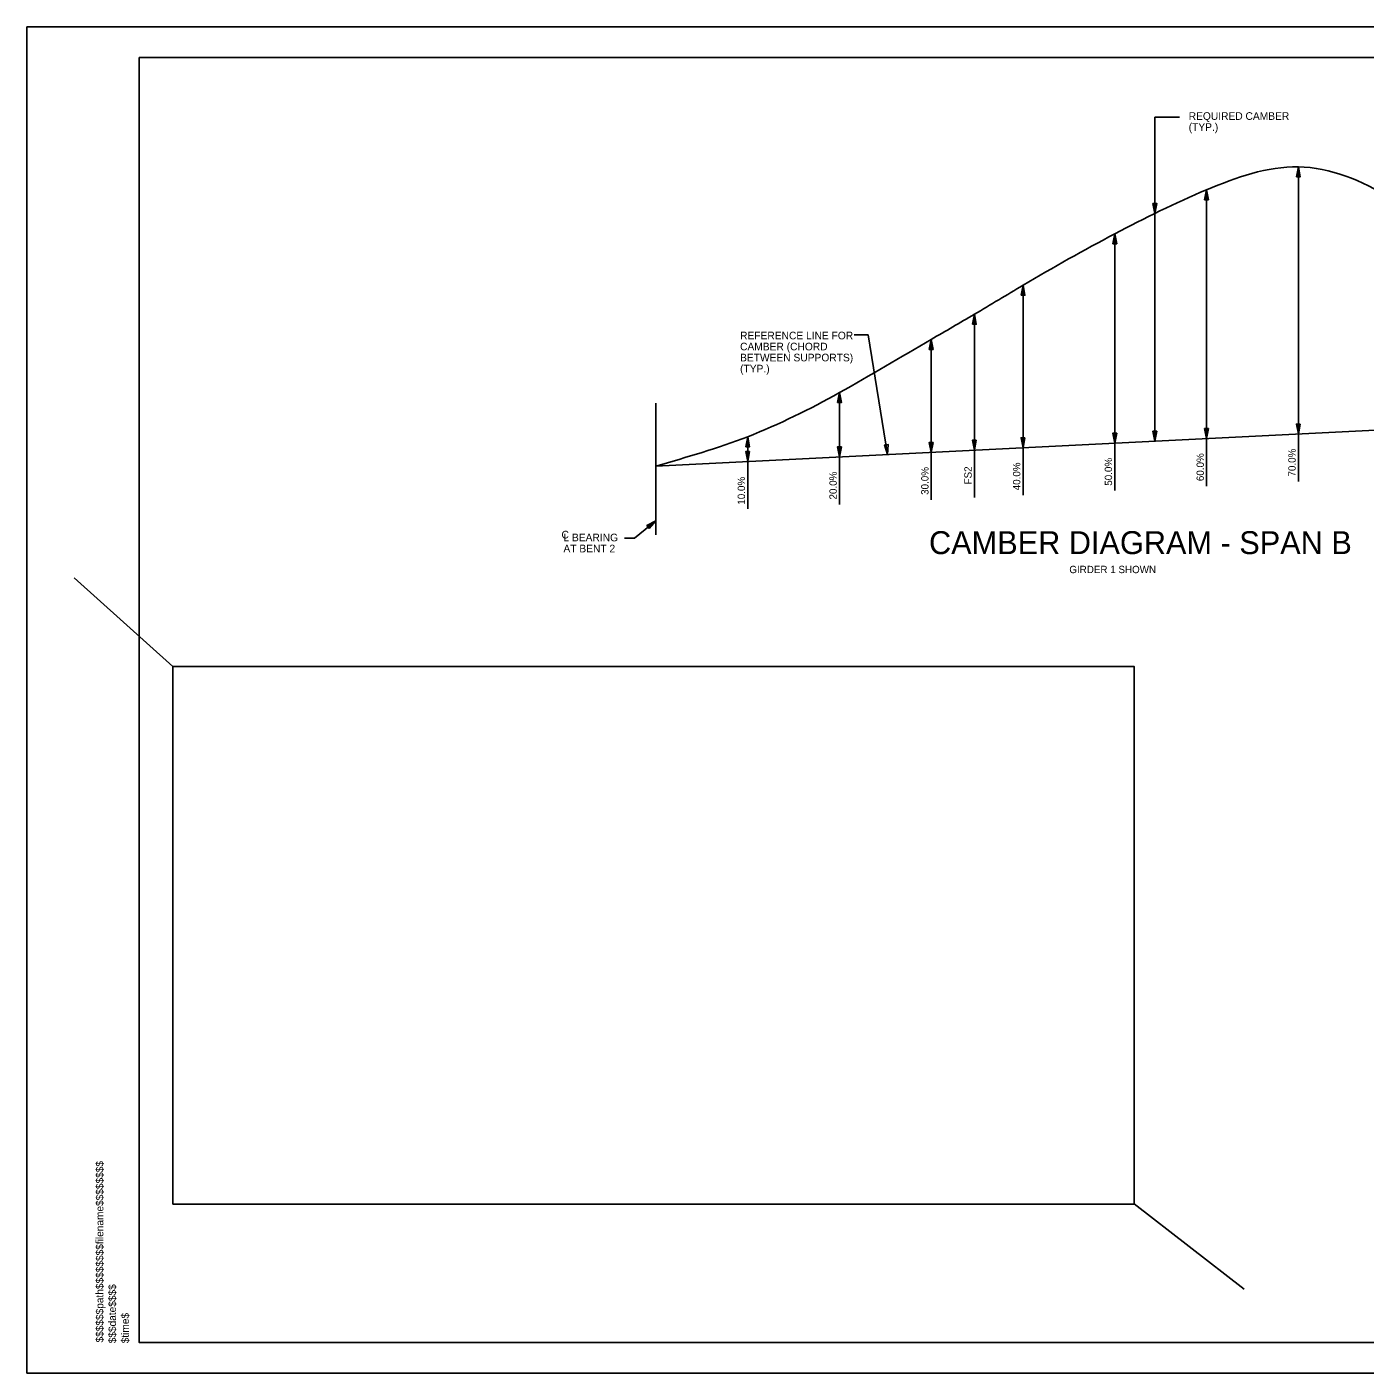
# Model space of a CAD drawing. Extents: x -125.5 to -89.4, y -5.1 to 16.9.
# Drawn here: x -125.53 to -103.66, y -5.07 to 16.93 of the extents above; entities that cross this region are included whole.
import ezdxf

# ---------------------------------------------------------------- set-up
doc = ezdxf.new("R2010")
doc.units = 0
for name, color, linetype in [('BR_AUTO DIMENSION', 7, 'Continuous'), ('BR_BORDER LINES', 7, 'Continuous'), ('BR_CENTER LINES', 7, 'Continuous'), ('BR_TABLE LINES', 7, 'Continuous'), ('BR_TEXT', 7, 'Continuous'), ('Level 31', 7, 'Continuous'), ('RD_SHT_ID', 7, 'Continuous')]:
    doc.layers.add(name, color=color, linetype=linetype)

msp = doc.modelspace()

# ---------------------------------------------------------------- linework, layer by layer
at = {"layer": 'BR_AUTO DIMENSION'}
for p, q in [((-107.098, 15.46), (-106.696, 15.46)), ((-107.098, 10.165), (-107.098, 15.46)), ((-112.01, 11.901), (-111.781, 11.901)), ((-111.781, 11.901), (-111.467, 9.946)), ((-115.605, 8.58), (-115.253, 8.86)), ((-115.765, 8.58), (-115.605, 8.58))]:
    msp.add_line(p, q, dxfattribs=at)
for points in [[(-104.785, 14.484), (-104.753, 14.647), (-104.722, 14.484)], [(-106.285, 14.109), (-106.253, 14.272), (-106.222, 14.109)], [(-107.129, 14.049), (-107.098, 13.887), (-107.066, 14.049)], [(-107.785, 13.389), (-107.753, 13.552), (-107.722, 13.389)], [(-109.285, 12.549), (-109.253, 12.712), (-109.222, 12.549)], [(-110.08, 12.075), (-110.048, 12.237), (-110.017, 12.075)], [(-110.785, 11.664), (-110.753, 11.827), (-110.722, 11.664)], [(-112.285, 10.794), (-112.253, 10.957), (-112.222, 10.794)], [(-106.222, 10.369), (-106.253, 10.207), (-106.285, 10.369)], [(-104.722, 10.444), (-104.753, 10.282), (-104.785, 10.444)], [(-113.785, 10.074), (-113.753, 10.237), (-113.722, 10.074)], [(-110.722, 10.144), (-110.753, 9.982), (-110.785, 10.144)], [(-110.017, 10.18), (-110.048, 10.017), (-110.08, 10.18)], [(-109.222, 10.219), (-109.253, 10.057), (-109.285, 10.219)], [(-107.722, 10.294), (-107.753, 10.132), (-107.785, 10.294)], [(-107.129, 10.327), (-107.098, 10.165), (-107.066, 10.327)], [(-113.722, 9.994), (-113.753, 9.832), (-113.785, 9.994)], [(-112.222, 10.069), (-112.253, 9.907), (-112.285, 10.069)], [(-111.519, 10.103), (-111.467, 9.946), (-111.457, 10.111)], [(-115.362, 8.735), (-115.253, 8.86), (-115.401, 8.785)]]:
    msp.add_lwpolyline(points, close=True, dxfattribs=at)
at = {"layer": 'BR_BORDER LINES'}
for p, q in [((-90.033, 16.434), (-123.699, 16.434)), ((-123.699, -4.566), (-123.699, 16.434)), ((-123.699, -4.566), (-90.033, -4.566))]:
    msp.add_line(p, q, dxfattribs=at)
at = {"layer": 'BR_CENTER LINES'}
msp.add_line((-115.253, 8.633), (-115.253, 10.783), dxfattribs=at)
at = {"layer": 'BR_TABLE LINES'}
for p, q in [((-104.753, 9.506), (-104.753, 14.647)), ((-106.253, 9.431), (-106.253, 14.272)), ((-107.753, 9.356), (-107.753, 13.552)), ((-109.253, 9.281), (-109.253, 12.712)), ((-110.048, 9.241), (-110.048, 12.237)), ((-110.753, 9.206), (-110.753, 11.827)), ((-112.253, 9.131), (-112.253, 10.957)), ((-100.24, 10.507), (-115.253, 9.757)), ((-113.753, 9.056), (-113.753, 10.237))]:
    msp.add_line(p, q, dxfattribs=at)
msp.add_lwpolyline([(-123.699, 16.434), (-90.033, 16.434), (-90.033, -4.566), (-123.699, -4.566)], close=True, dxfattribs=at)
msp.add_spline([(-115.253, 9.757), (-113.753, 10.237), (-112.253, 10.957), (-110.753, 11.827), (-110.048, 12.237), (-109.253, 12.712), (-107.753, 13.552), (-106.253, 14.272), (-104.753, 14.647), (-103.253, 14.137), (-101.753, 12.742), (-100.24, 10.507)], degree=3, dxfattribs=at)
at = {"layer": 'Level 31'}
for p, q in [((-89.533, 16.934), (-125.533, 16.934)), ((-123.148, 6.483), (-124.762, 7.928)), ((-107.438, -2.299), (-105.638, -3.695))]:
    msp.add_line(p, q, dxfattribs=at)
msp.add_lwpolyline([(-125.533, 16.934), (-125.533, -5.066), (-89.533, -5.066), (-89.533, 16.934)], dxfattribs=at)
msp.add_lwpolyline([(-123.148, -2.307), (-107.438, -2.307), (-107.438, 6.483), (-123.148, 6.483)], close=True, dxfattribs=at)

# ---------------------------------------------------------------- texts
at = {"layer": 'BR_AUTO DIMENSION'}
for s, p in [('REQUIRED CAMBER', (-106.545, 15.415)), ('(TYP.)', (-106.545, 15.235)), ('REFERENCE LINE FOR', (-113.877, 11.828)), ('CAMBER (CHORD', (-113.877, 11.648)), ('BETWEEN SUPPORTS)', (-113.877, 11.468)), ('(TYP.)', (-113.877, 11.287)), ('C', (-116.796, 8.574)), ('L BEARING', (-116.764, 8.527)), ('AT BENT 2', (-116.764, 8.347))]:
    msp.add_text(s, height=0.125, dxfattribs=at).set_placement(p)
at = {"layer": 'BR_TEXT'}
for s, p in [('60.0%', (-106.297, 9.511)), ('70.0%', (-104.797, 9.586)), ('30.0%', (-110.797, 9.286)), ('FS2', (-110.092, 9.457)), ('40.0%', (-109.297, 9.361)), ('50.0%', (-107.797, 9.436)), ('10.0%', (-113.797, 9.126)), ('20.0%', (-112.297, 9.211))]:
    msp.add_text(s, height=0.12, rotation=90, dxfattribs=at).set_placement(p)
for s, height, p in [('CAMBER DIAGRAM - SPAN B', 0.375, (-110.789, 8.318)), ('GIRDER 1 SHOWN', 0.12, (-108.496, 8.007))]:
    msp.add_text(s, height=height, dxfattribs=at).set_placement(p)
at = {"layer": 'RD_SHT_ID'}
for s, height, p in [('$$$$$$path$$$$$$$$filename$$$$$$$$', 0.12347, (-124.283, -4.566)), ('$$$date$$$$', 0.12347, (-124.077, -4.579)), ('$time$', 0.1235, (-123.866, -4.579))]:
    msp.add_text(s, height=height, rotation=90, dxfattribs=at).set_placement(p)

doc.saveas('drawing.dxf')
